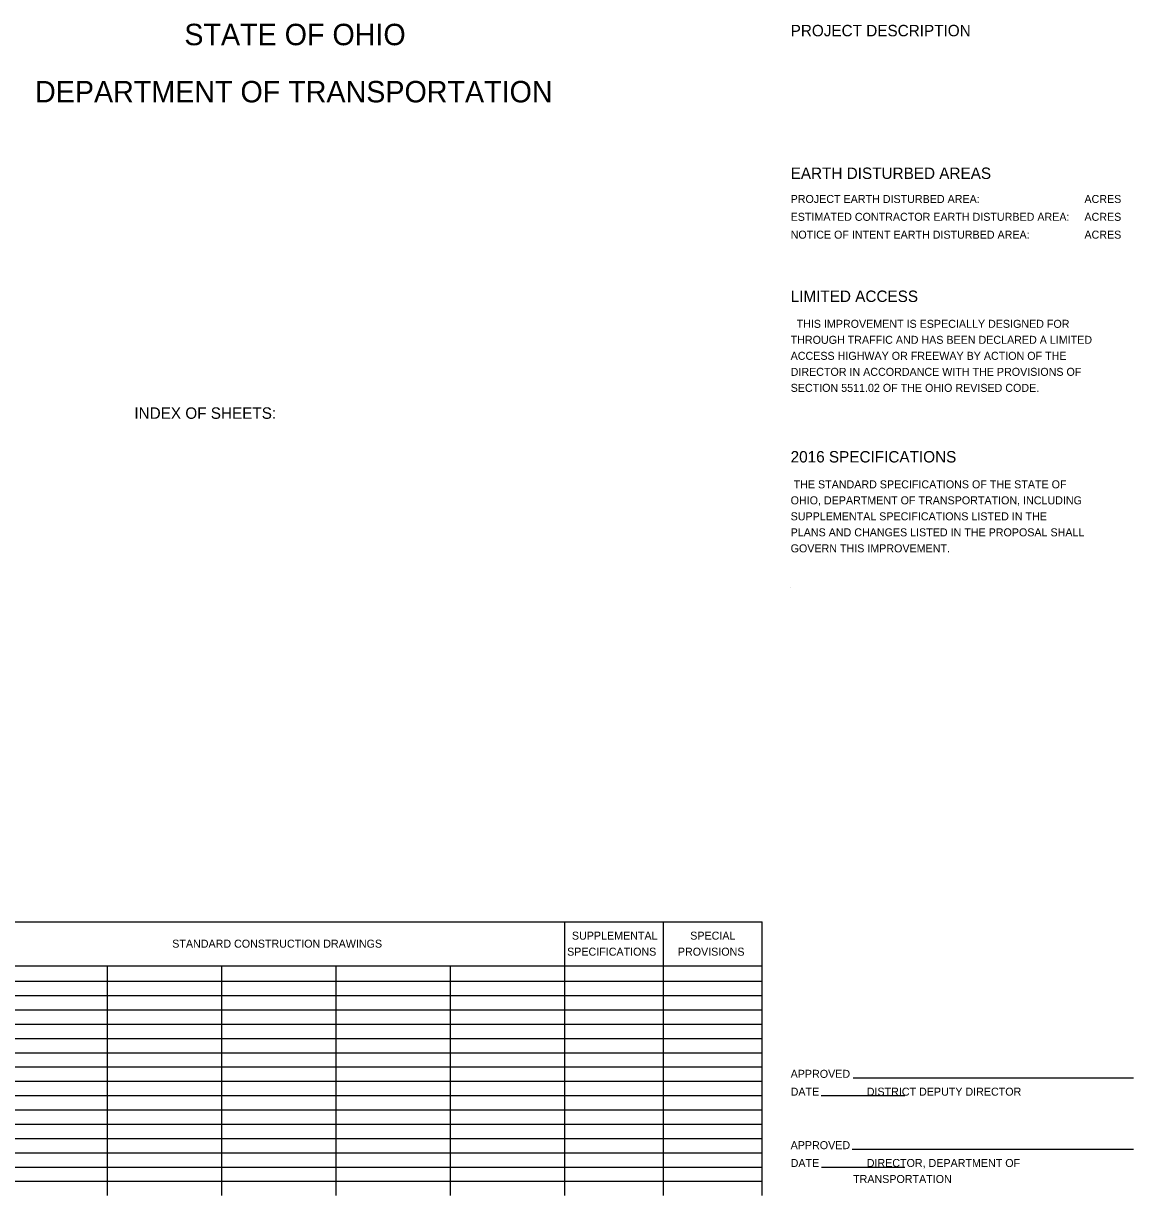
# Model space of a CAD drawing. Extents: x -97 to 34, y -21 to 22.
# Drawn here: x -87.38 to -67.96, y -21.41 to -0.91 of the extents above; entities that cross this region are included whole.
import ezdxf

# ---------------------------------------------------------------- set-up
doc = ezdxf.new("R2010")
doc.units = 0
doc.layers.add('SH_Data', color=7, linetype='Continuous')

msp = doc.modelspace()

# ---------------------------------------------------------------- linework, layer by layer
at = {"layer": 'SH_Data'}
for p, q in [((-73.956, -10.773), (-73.956, -10.773)), ((-87.906, -16.622), (-74.456, -16.622)), ((-77.906, -21.414), (-77.906, -16.622)), ((-76.181, -21.414), (-76.181, -16.622)), ((-74.456, -21.414), (-74.456, -16.622)), ((-87.906, -17.393), (-74.456, -17.393)), ((-85.906, -21.414), (-85.906, -17.393)), ((-83.906, -21.414), (-83.906, -17.393)), ((-81.906, -21.414), (-81.906, -17.393)), ((-79.906, -21.414), (-79.906, -17.393)), ((-87.906, -17.664), (-74.456, -17.664)), ((-87.906, -17.914), (-74.456, -17.914)), ((-87.906, -18.164), (-74.456, -18.164)), ((-87.906, -18.414), (-74.456, -18.414)), ((-87.906, -18.664), (-74.456, -18.664)), ((-87.906, -18.914), (-74.456, -18.914)), ((-87.906, -19.164), (-74.456, -19.164)), ((-87.906, -19.414), (-74.456, -19.414)), ((-72.862, -19.354), (-67.956, -19.354)), ((-87.906, -19.664), (-74.456, -19.664)), ((-73.423, -19.666), (-71.956, -19.666)), ((-87.906, -19.914), (-74.456, -19.914)), ((-87.906, -20.164), (-74.456, -20.164)), ((-87.906, -20.414), (-74.456, -20.414)), ((-87.906, -20.664), (-74.456, -20.664)), ((-72.877, -20.602), (-67.956, -20.602)), ((-87.906, -20.914), (-74.456, -20.914)), ((-73.414, -20.914), (-71.956, -20.914)), ((-87.906, -21.164), (-74.456, -21.164))]:
    msp.add_line(p, q, dxfattribs=at)

# ---------------------------------------------------------------- texts
for s, height, p in [('STATE OF OHIO', 0.375, (-84.564, -1.289)), ('PROJECT DESCRIPTION', 0.2, (-73.956, -1.133)), ('DEPARTMENT OF TRANSPORTATION', 0.375, (-87.176, -2.289)), ('EARTH DISTURBED AREAS', 0.2, (-73.956, -3.629)), ('PROJECT EARTH DISTURBED AREA:', 0.14, (-73.956, -4.049)), ('     ACRES', 0.14, (-69.076, -4.049)), ('ESTIMATED CONTRACTOR EARTH DISTURBED AREA:', 0.14, (-73.956, -4.361)), ('     ACRES', 0.14, (-69.076, -4.361)), ('NOTICE OF INTENT EARTH DISTURBED AREA:', 0.14, (-73.956, -4.673)), ('     ACRES', 0.14, (-69.076, -4.673)), ('LIMITED ACCESS', 0.2, (-73.956, -5.781)), ('  THIS IMPROVEMENT IS ESPECIALLY DESIGNED FOR', 0.14, (-73.956, -6.233)), ('THROUGH TRAFFIC AND HAS BEEN DECLARED A LIMITED', 0.14, (-73.956, -6.513)), ('ACCESS HIGHWAY OR FREEWAY BY ACTION OF THE', 0.14, (-73.956, -6.793)), ('DIRECTOR IN ACCORDANCE WITH THE PROVISIONS OF', 0.14, (-73.956, -7.073)), ('SECTION 5511.02 OF THE OHIO REVISED CODE.', 0.14, (-73.956, -7.353)), ('INDEX OF SHEETS:', 0.2, (-85.439, -7.825)), ('2016 SPECIFICATIONS', 0.2, (-73.956, -8.589)), (' THE STANDARD SPECIFICATIONS OF THE STATE OF', 0.14, (-73.956, -9.041)), ('OHIO, DEPARTMENT OF TRANSPORTATION, INCLUDING', 0.14, (-73.956, -9.321)), ('SUPPLEMENTAL SPECIFICATIONS LISTED IN THE', 0.14, (-73.956, -9.601)), ('PLANS AND CHANGES LISTED IN THE PROPOSAL SHALL', 0.14, (-73.956, -9.881)), ('GOVERN THIS IMPROVEMENT.', 0.14, (-73.956, -10.161)), ('SUPPLEMENTAL', 0.14, (-77.783, -16.937)), ('SPECIAL', 0.14, (-75.713, -16.937)), ('STANDARD CONSTRUCTION DRAWINGS', 0.14, (-84.776, -17.077)), ('SPECIFICATIONS', 0.14, (-77.867, -17.217)), ('PROVISIONS', 0.14, (-75.929, -17.217)), ('APPROVED', 0.14, (-73.956, -19.354)), ('DATE                DISTRICT DEPUTY DIRECTOR', 0.14, (-73.956, -19.666)), ('APPROVED', 0.14, (-73.956, -20.602)), ('DATE                DIRECTOR, DEPARTMENT OF', 0.14, (-73.956, -20.914)), ('                     TRANSPORTATION', 0.14, (-73.956, -21.194))]:
    msp.add_text(s, height=height, dxfattribs=at).set_placement(p)

doc.saveas('drawing.dxf')
